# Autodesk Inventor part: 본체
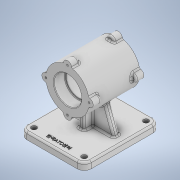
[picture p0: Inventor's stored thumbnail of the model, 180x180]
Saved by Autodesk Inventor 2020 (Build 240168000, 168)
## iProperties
Created: 2022-11
Part Number: 본체
Material: 일반
Document SubType Name: Modeling
Designer: owner
Density: 1 g/cm^3
Appearance: 기본값
Author: owner
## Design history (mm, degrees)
sketch "스케치1"
  geometry: C1 r 37 at (0, 0); 1 further point
  constraints: 1 centre point, 1 coincident
  dimensions: "d0" = 74 diameter of C1
extrude "돌출1" new body sketch "스케치1" stored distance "d1" = 87; taper "d2" = 0 deg
sketch "스케치2"
  geometry: C1 r 37 at (0, 0) reference; 2 further points
  constraints: 1 coincident
hole "구멍1" sketch "스케치2" at (0, 0) diameter "d3" = 42; stored, may be unused: countersink angle "d7" = 90 deg, drill point angle "d9" = 0 deg; dims "d4" = 6, "d5" = 47, "d6" = 19, "d8" = 10
sketch "스케치3"
  geometry: C1 r 21 at (0, 0) reference; C2 r 23.5 at (0, 0); 1 further point
  constraints: 1 centre point, 1 coincident
  dimensions: "d10" = 47 diameter of C2
extrude "돌출2" cut sketch "스케치3" distance "d11" = 19; taper "d12" = 0 deg
sketch "스케치4"
  geometry: C1 r 7 at (0, 37); 4 further points
  constraints: 1 centre point, 1 vertical alignment, 2 other
  dimensions: "d13" = 14 diameter of C1
extrude "돌출3" join sketch "스케치4" distance "d14" = 14; taper "d15" = 0 deg
sketch "스케치5"
  geometry: A1 r 7 centre (0, 37) between (6.969, 36.338) and (-6.969, 36.338) reference; 2 further points
  constraints: 1 coincident
hole "구멍2" sketch "스케치5" at (0, 37) diameter "d19" = 3.242; stored, may be unused: countersink angle "d23" = 90 deg, drill point angle "d25" = 118 deg; dims "d20" = 8, "d21" = 47, "d22" = 19, "d24" = 10
sketch "스케치6"
  geometry: L1 (-55, -70)-(55, -70); L2 (55, -70)-(55, -82); L3 (55, -82)-(-55, -82); L4 (-55, -82)-(-55, -70); 2 further points
  constraints: 8 end point, 2 parallel, 1 horizontal, 1 midpoint, 1 perpendicular, 1 vertical alignment
  dimensions: "d29" = 110 distance of L2.end L3.end; "d30" = 12 distance of L3.end L1.start; "d31" = 82 distance from line of point (0, 0) L3
extrude "돌출4" join sketch "스케치6" distance "d32" = 70; taper "d33" = 0 deg
sketch "스케치7"
  geometry: L1 (-55, -70)-(55, -70) reference; L2 (-55, -82)-(-55, -70) reference; L3 (55, -70)-(55, -82) reference; L4 (55, -82)-(-55, -82) reference; 1 further point
extrude "돌출5" join sketch "스케치7" distance "d34" = 60; taper "d35" = 0 deg
fillet "모깎기1" dims "d36" = 12
sketch "스케치8"
  geometry: A1 r 12 centre (0, 12) between (-12, 12) and (0, 0) reference; A2 r 12 centre (86, 12) between (86, 0) and (98, 12) reference; A3 r 12 centre (86, 118) between (98, 118) and (86, 130) reference; A4 r 12 centre (0, 118) between (0, 130) and (-12, 118) reference; 5 further points
  constraints: 4 coincident
hole "구멍3" sketch "스케치8" at (0, 12), (86, 12), (86, 118), (0, 118) diameter "d37" = 9; stored, may be unused: countersink angle "d41" = 90 deg, drill point angle "d43" = 118 deg; dims "d38" = 8, "d39" = 47, "d40" = 19, "d42" = 10
sketch "스케치9"
  geometry: L1 (43, -70)-(55, -70) reference; L2 (-43, -70)-(43, -70) reference; L3 (-55, -70)-(-43, -70) reference; L4 (43, -70)-(-43, -70) reference; L5 (41, -70)-(25.336, -26.964); L6 (-25.336, -26.964)-(-41, -70); A1 r 37 centre (0, 0) between (6.969, -36.338) and (36.338, -6.969) reference; A2 r 37 centre (0, 0) between (-36.338, -6.969) and (-6.969, -36.338) reference; A3 r 37 centre (0, 0) between (-6.969, -36.338) and (6.969, -36.338) reference; 3 further points
  constraints: 4 end point, 2 point on circle, 2 point on line
  dimensions: "d44" = 14 distance of L5.start L1.end; "d45" = 14 distance of L3.start L6.end; "d46" = 110 deg angle of L1 L5; "d47" = 110 deg angle of L3 L6
extrude "돌출6" join sketch "스케치9" stored distance "d48" = 10; taper "d49" = 0 deg
sketch "스케치10"
  geometry: L1 (-70, -48)-(-70, 58) reference; L2 (-70, -48)-(-70, 58) reference; L3 (-70, 20)-(-48.714, 20); 1 further point
  constraints: 2 end point, 1 perpendicular, 1 point on line
  dimensions: "d50" = 20 vertical distance of L3.start point (0, 0)
feature "리브1" sketch "스케치10" dims "d51" = 1, "d52" = 10, "d53" = 0, "d54" = 0, "d55" = 1, "d56" = 1
fillet "모깎기2" dims "d57" = 3
fillet "모깎기3" dims "d58" = 3
fillet "모깎기4" dims "d62" = 3
fillet "모깎기5" dims "d63" = 3
fillet "모깎기6" dims "d70" = 3
fillet "모깎기7" dims "d71" = 3
sketch "스케치11"
  geometry: L1 (0, -3)-(86, -3) reference; C1 r 4.5 at (86, 9) reference; 3 further points
  constraints: 1 midpoint, 1 vertical alignment, 1 other
  dimensions: "d72" = 12 distance of point (43, -3) point (43, 9)
feature "엠보싱1" sketch "스케치11" dims "d1" = 87, "d73" = 0.5, "d74" = 0
fillet "모깎기8" dims "d78" = 1
chamfer "모따기3" distance "d79" = 1; stored, may be unused: second distance "d80" = 2, angle "d81" = 45 deg
node "솔리드1"
pattern_circular "원형 패턴1" dims angle "d17" = 360 deg
pattern_circular "원형 패턴2" dims angle "d27" = 360 deg
mirror "미러1"
mirror "미러2"
pattern_circular "원형 패턴3" dims angle "d60" = 360 deg
pattern_circular "원형 패턴4" dims angle "d65" = 360 deg
feature "A9D066F2-1C7D-4E18-AEED-F7BC21143FA4" dims "d3" = 42, "d4" = 6, "d5" = 47, "d6" = 19, "d7" = 90 deg, "d8" = 10, "d9" = 0
